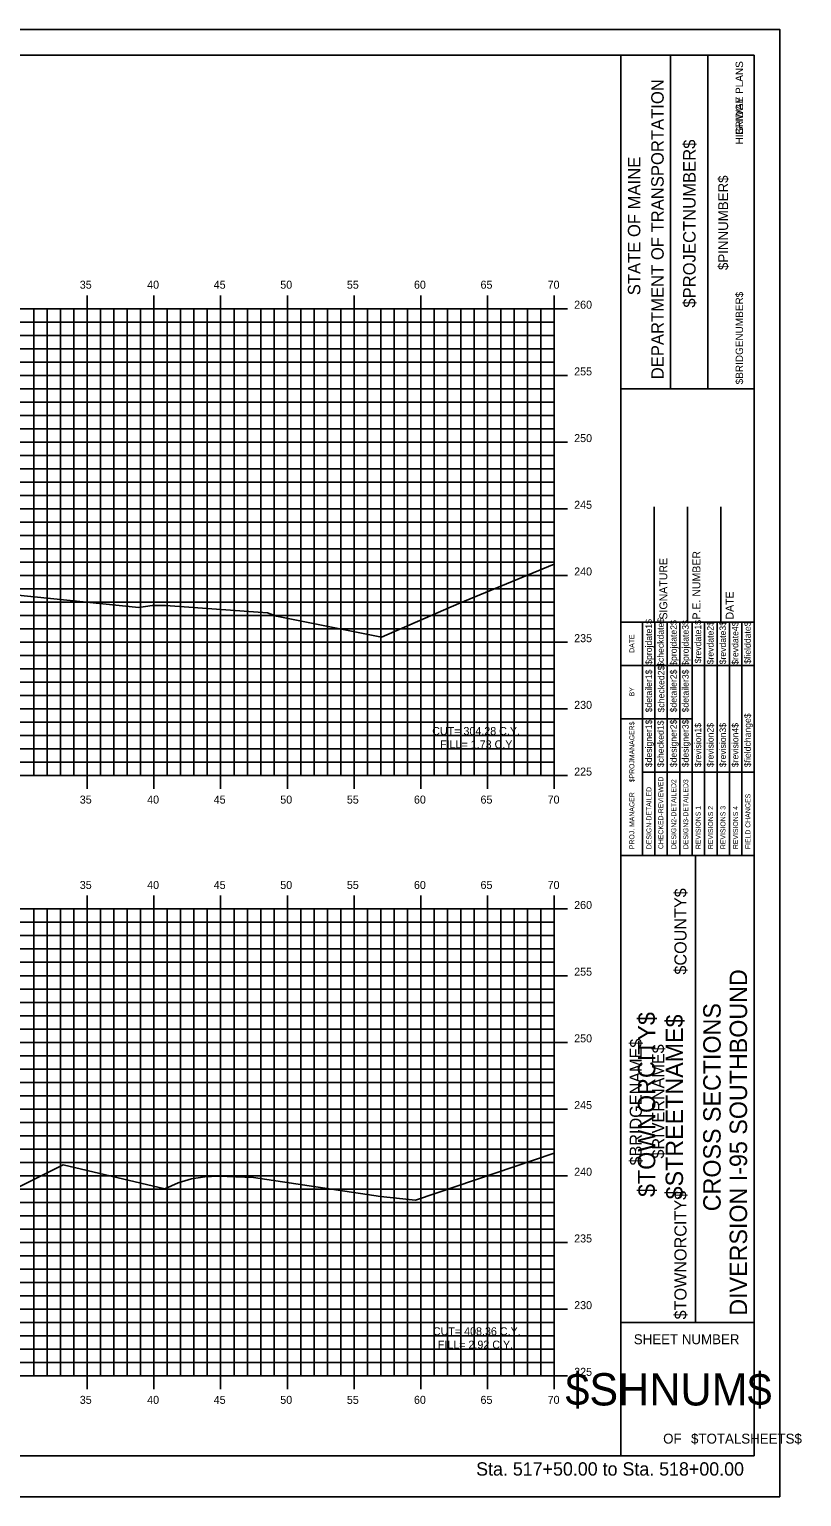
# Model space of a CAD drawing. Extents: x 1170543 to 1177585, y 609599 to 610623.
# Drawn here: x 1173835.4 to 1173893.3, y 609598.8 to 609708.8 of the extents above; entities that cross this region are included whole.
import ezdxf

# ---------------------------------------------------------------- set-up
doc = ezdxf.new("R2010")
doc.units = 0
for name, color, linetype in [('BORDER', 7, 'Continuous'), ('BRIDGE_TITLE', 7, 'Continuous'), ('D_Roadway_Centerline_Text', 7, 'Continuous'), ('H_V ANNOTATION', 7, 'Continuous'), ('HIGHWAY_TITLE', 7, 'Continuous'), ('MAJOR', 7, 'Continuous'), ('MINOR', 7, 'Continuous'), ('PLOT BOUNDARY', 7, 'Continuous'), ('S_Roadway_Centerline', 7, 'Continuous')]:
    doc.layers.add(name, color=color, linetype=linetype)

msp = doc.modelspace()

# ---------------------------------------------------------------- linework, layer by layer
at = {"layer": 'BORDER'}
for p, q in [((1173889.77, 609706.87), (1173729.77, 609706.87)), ((1173879.77, 609601.88), (1173879.77, 609706.88)), ((1173883.5, 609681.87), (1173883.5, 609706.87)), ((1173886.3, 609681.87), (1173886.3, 609706.87)), ((1173889.77, 609601.88), (1173889.77, 609706.88)), ((1173879.77, 609681.87), (1173889.77, 609681.87)), ((1173882.27, 609664.38), (1173882.27, 609673.02)), ((1173884.77, 609664.38), (1173884.77, 609673.02)), ((1173887.27, 609664.38), (1173887.27, 609673.02)), ((1173879.77, 609664.38), (1173889.77, 609664.38)), ((1173879.77, 609646.88), (1173889.77, 609646.88)), ((1173885.36, 609611.88), (1173885.36, 609646.88)), ((1173879.77, 609611.88), (1173889.77, 609611.88)), ((1173729.77, 609601.87), (1173889.77, 609601.87))]:
    msp.add_line(p, q, dxfattribs=at)
for points in [[(1173881.39, 609661.13), (1173881.39, 609664.38)], [(1173882.32, 609646.88), (1173882.32, 609664.38)], [(1173883.25, 609664.38), (1173883.25, 609646.88)], [(1173884.18, 609646.88), (1173884.18, 609664.38)], [(1173885.12, 609646.88), (1173885.12, 609664.38)], [(1173886.05, 609646.88), (1173886.05, 609664.38)], [(1173886.98, 609646.88), (1173886.98, 609664.38)], [(1173887.91, 609646.88), (1173887.91, 609664.38)], [(1173888.84, 609646.88), (1173888.84, 609664.38)], [(1173881.39, 609646.88), (1173881.39, 609663.67)], [(1173879.77, 609661.13), (1173889.77, 609661.13)], [(1173879.77, 609657.13), (1173881.39, 609657.13)], [(1173881.39, 609657.13), (1173885.12, 609657.13)], [(1173881.39, 609653.13), (1173889.77, 609653.13)]]:
    msp.add_lwpolyline(points, dxfattribs=at)
at = {"layer": 'MAJOR'}
for p, q in [((1173839.77, 609688.87), (1173839.77, 609687.87)), ((1173844.77, 609688.87), (1173844.77, 609687.87)), ((1173849.77, 609688.87), (1173849.77, 609687.87)), ((1173854.77, 609688.87), (1173854.77, 609687.87)), ((1173859.77, 609688.87), (1173859.77, 609687.87)), ((1173864.77, 609688.87), (1173864.77, 609687.87)), ((1173869.77, 609688.87), (1173869.77, 609687.87)), ((1173874.77, 609688.87), (1173874.77, 609687.87)), ((1173734.77, 609687.87), (1173874.77, 609687.87)), ((1173734.77, 609687.87), (1173874.77, 609687.87)), ((1173839.77, 609652.87), (1173839.77, 609687.87)), ((1173844.77, 609652.87), (1173844.77, 609687.87)), ((1173849.77, 609652.87), (1173849.77, 609687.87)), ((1173854.77, 609652.87), (1173854.77, 609687.87)), ((1173859.77, 609652.87), (1173859.77, 609687.87)), ((1173864.77, 609652.87), (1173864.77, 609687.87)), ((1173869.77, 609652.87), (1173869.77, 609687.87)), ((1173875.78, 609687.87), (1173873.77, 609687.87)), ((1173874.77, 609652.87), (1173874.77, 609687.87)), ((1173874.77, 609652.87), (1173874.77, 609687.87)), ((1173734.77, 609682.87), (1173874.77, 609682.87)), ((1173875.78, 609682.87), (1173873.77, 609682.87)), ((1173734.77, 609677.87), (1173874.77, 609677.87)), ((1173875.78, 609677.87), (1173873.77, 609677.87)), ((1173734.77, 609672.87), (1173874.77, 609672.87)), ((1173875.78, 609672.87), (1173873.77, 609672.87)), ((1173734.77, 609667.87), (1173874.77, 609667.87)), ((1173875.78, 609667.87), (1173873.77, 609667.87)), ((1173734.77, 609662.87), (1173874.77, 609662.87)), ((1173875.78, 609662.87), (1173873.77, 609662.87)), ((1173734.77, 609657.87), (1173874.77, 609657.87)), ((1173875.78, 609657.87), (1173873.77, 609657.87)), ((1173734.77, 609652.87), (1173874.77, 609652.87)), ((1173734.77, 609652.87), (1173874.77, 609652.87)), ((1173839.77, 609651.87), (1173839.77, 609652.87)), ((1173844.77, 609651.87), (1173844.77, 609652.87)), ((1173849.77, 609651.87), (1173849.77, 609652.87)), ((1173854.77, 609651.87), (1173854.77, 609652.87)), ((1173859.77, 609651.87), (1173859.77, 609652.87)), ((1173864.77, 609651.87), (1173864.77, 609652.87)), ((1173869.77, 609651.87), (1173869.77, 609652.87)), ((1173875.78, 609652.87), (1173873.77, 609652.87)), ((1173874.77, 609651.87), (1173874.77, 609652.87)), ((1173839.77, 609643.87), (1173839.77, 609642.87)), ((1173844.77, 609643.87), (1173844.77, 609642.87)), ((1173849.77, 609643.87), (1173849.77, 609642.87)), ((1173854.77, 609643.87), (1173854.77, 609642.87)), ((1173859.77, 609643.87), (1173859.77, 609642.87)), ((1173864.77, 609643.87), (1173864.77, 609642.87)), ((1173869.77, 609643.87), (1173869.77, 609642.87)), ((1173874.77, 609643.87), (1173874.77, 609642.87)), ((1173734.77, 609642.87), (1173874.77, 609642.87)), ((1173734.77, 609642.87), (1173874.77, 609642.87)), ((1173839.77, 609607.87), (1173839.77, 609642.87)), ((1173844.77, 609607.87), (1173844.77, 609642.87)), ((1173849.77, 609607.87), (1173849.77, 609642.87)), ((1173854.77, 609607.87), (1173854.77, 609642.87)), ((1173859.77, 609607.87), (1173859.77, 609642.87)), ((1173864.77, 609607.87), (1173864.77, 609642.87)), ((1173869.77, 609607.87), (1173869.77, 609642.87)), ((1173875.78, 609642.87), (1173873.77, 609642.87)), ((1173874.77, 609607.87), (1173874.77, 609642.87)), ((1173874.77, 609607.87), (1173874.77, 609642.87)), ((1173734.77, 609637.87), (1173874.77, 609637.87)), ((1173875.78, 609637.87), (1173873.77, 609637.87)), ((1173734.77, 609632.87), (1173874.77, 609632.87)), ((1173875.78, 609632.87), (1173873.77, 609632.87)), ((1173734.77, 609627.87), (1173874.77, 609627.87)), ((1173875.78, 609627.87), (1173873.77, 609627.87)), ((1173734.77, 609622.87), (1173874.77, 609622.87)), ((1173875.78, 609622.87), (1173873.77, 609622.87)), ((1173734.77, 609617.87), (1173874.77, 609617.87)), ((1173875.78, 609617.87), (1173873.77, 609617.87)), ((1173734.77, 609612.87), (1173874.77, 609612.87)), ((1173875.78, 609612.87), (1173873.77, 609612.87)), ((1173734.77, 609607.87), (1173874.77, 609607.87)), ((1173734.77, 609607.87), (1173874.77, 609607.87)), ((1173839.77, 609606.87), (1173839.77, 609607.87)), ((1173844.77, 609606.87), (1173844.77, 609607.87)), ((1173849.77, 609606.87), (1173849.77, 609607.87)), ((1173854.77, 609606.87), (1173854.77, 609607.87)), ((1173859.77, 609606.87), (1173859.77, 609607.87)), ((1173864.77, 609606.87), (1173864.77, 609607.87)), ((1173869.77, 609606.87), (1173869.77, 609607.87)), ((1173875.78, 609607.87), (1173873.77, 609607.87)), ((1173874.77, 609606.87), (1173874.77, 609607.87))]:
    msp.add_line(p, q, dxfattribs=at)
at = {"layer": 'MINOR'}
for p, q in [((1173835.77, 609652.87), (1173835.77, 609687.87)), ((1173836.77, 609652.87), (1173836.77, 609687.87)), ((1173837.77, 609652.87), (1173837.77, 609687.87)), ((1173838.77, 609652.87), (1173838.77, 609687.87)), ((1173840.77, 609652.87), (1173840.77, 609687.87)), ((1173841.77, 609652.87), (1173841.77, 609687.87)), ((1173842.77, 609652.87), (1173842.77, 609687.87)), ((1173843.77, 609652.87), (1173843.77, 609687.87)), ((1173845.77, 609652.87), (1173845.77, 609687.87)), ((1173846.77, 609652.87), (1173846.77, 609687.87)), ((1173847.77, 609652.87), (1173847.77, 609687.87)), ((1173848.77, 609652.87), (1173848.77, 609687.87)), ((1173850.77, 609652.87), (1173850.77, 609687.87)), ((1173851.77, 609652.87), (1173851.77, 609687.87)), ((1173852.77, 609652.87), (1173852.77, 609687.87)), ((1173853.77, 609652.87), (1173853.77, 609687.87)), ((1173855.77, 609652.87), (1173855.77, 609687.87)), ((1173856.77, 609652.87), (1173856.77, 609687.87)), ((1173857.77, 609652.87), (1173857.77, 609687.87)), ((1173858.77, 609652.87), (1173858.77, 609687.87)), ((1173860.77, 609652.87), (1173860.77, 609687.87)), ((1173861.77, 609652.87), (1173861.77, 609687.87)), ((1173862.77, 609652.87), (1173862.77, 609687.87)), ((1173863.77, 609652.87), (1173863.77, 609687.87)), ((1173865.77, 609652.87), (1173865.77, 609687.87)), ((1173866.77, 609652.87), (1173866.77, 609687.87)), ((1173867.77, 609652.87), (1173867.77, 609687.87)), ((1173868.77, 609652.87), (1173868.77, 609687.87)), ((1173870.77, 609652.87), (1173870.77, 609687.87)), ((1173871.77, 609652.87), (1173871.77, 609687.87)), ((1173872.77, 609652.87), (1173872.77, 609687.87)), ((1173873.77, 609652.87), (1173873.77, 609687.87)), ((1173734.77, 609686.87), (1173874.77, 609686.87)), ((1173874.77, 609686.87), (1173873.77, 609686.87)), ((1173734.77, 609685.87), (1173874.77, 609685.87)), ((1173874.77, 609685.87), (1173873.77, 609685.87)), ((1173734.77, 609684.87), (1173874.77, 609684.87)), ((1173734.77, 609683.87), (1173874.77, 609683.87)), ((1173874.77, 609684.87), (1173873.77, 609684.87)), ((1173874.77, 609683.87), (1173873.77, 609683.87)), ((1173734.77, 609681.87), (1173874.77, 609681.87)), ((1173874.77, 609681.87), (1173873.77, 609681.87)), ((1173734.77, 609680.87), (1173874.77, 609680.87)), ((1173874.77, 609680.87), (1173873.77, 609680.87)), ((1173734.77, 609679.87), (1173874.77, 609679.87)), ((1173874.77, 609679.87), (1173873.77, 609679.87)), ((1173734.77, 609678.87), (1173874.77, 609678.87)), ((1173874.77, 609678.87), (1173873.77, 609678.87)), ((1173734.77, 609676.87), (1173874.77, 609676.87)), ((1173874.77, 609676.87), (1173873.77, 609676.87)), ((1173734.77, 609675.87), (1173874.77, 609675.87)), ((1173874.77, 609675.87), (1173873.77, 609675.87)), ((1173734.77, 609674.87), (1173874.77, 609674.87)), ((1173874.77, 609674.87), (1173873.77, 609674.87)), ((1173734.77, 609673.87), (1173874.77, 609673.87)), ((1173874.77, 609673.87), (1173873.77, 609673.87)), ((1173734.77, 609671.87), (1173874.77, 609671.87)), ((1173874.77, 609671.87), (1173873.77, 609671.87)), ((1173734.77, 609670.87), (1173874.77, 609670.87)), ((1173874.77, 609670.87), (1173873.77, 609670.87)), ((1173734.77, 609669.87), (1173874.77, 609669.87)), ((1173874.77, 609669.87), (1173873.77, 609669.87)), ((1173734.77, 609668.87), (1173874.77, 609668.87)), ((1173874.77, 609668.87), (1173873.77, 609668.87)), ((1173734.77, 609666.87), (1173874.77, 609666.87)), ((1173874.77, 609666.87), (1173873.77, 609666.87)), ((1173734.77, 609665.87), (1173874.77, 609665.87)), ((1173874.77, 609665.87), (1173873.77, 609665.87)), ((1173734.77, 609664.87), (1173874.77, 609664.87)), ((1173874.77, 609664.87), (1173873.77, 609664.87)), ((1173734.77, 609663.87), (1173874.77, 609663.87)), ((1173874.77, 609663.87), (1173873.77, 609663.87)), ((1173734.77, 609661.87), (1173874.77, 609661.87)), ((1173874.77, 609661.87), (1173873.77, 609661.87)), ((1173734.77, 609660.87), (1173874.77, 609660.87)), ((1173874.77, 609660.87), (1173873.77, 609660.87)), ((1173734.77, 609659.87), (1173874.77, 609659.87)), ((1173874.77, 609659.87), (1173873.77, 609659.87)), ((1173734.77, 609658.87), (1173874.77, 609658.87)), ((1173874.77, 609658.87), (1173873.77, 609658.87)), ((1173734.77, 609656.87), (1173874.77, 609656.87)), ((1173874.77, 609656.87), (1173873.77, 609656.87)), ((1173734.77, 609655.87), (1173874.77, 609655.87)), ((1173874.77, 609655.87), (1173873.77, 609655.87)), ((1173734.77, 609654.87), (1173874.77, 609654.87)), ((1173874.77, 609654.87), (1173873.77, 609654.87)), ((1173734.77, 609653.87), (1173874.77, 609653.87)), ((1173874.77, 609653.87), (1173873.77, 609653.87)), ((1173835.77, 609607.87), (1173835.77, 609642.87)), ((1173836.77, 609607.87), (1173836.77, 609642.87)), ((1173837.77, 609607.87), (1173837.77, 609642.87)), ((1173838.77, 609607.87), (1173838.77, 609642.87)), ((1173840.77, 609607.87), (1173840.77, 609642.87)), ((1173841.77, 609607.87), (1173841.77, 609642.87)), ((1173842.77, 609607.87), (1173842.77, 609642.87)), ((1173843.77, 609607.87), (1173843.77, 609642.87)), ((1173845.77, 609607.87), (1173845.77, 609642.87)), ((1173846.77, 609607.87), (1173846.77, 609642.87)), ((1173847.77, 609607.87), (1173847.77, 609642.87)), ((1173848.77, 609607.87), (1173848.77, 609642.87)), ((1173850.77, 609607.87), (1173850.77, 609642.87)), ((1173851.77, 609607.87), (1173851.77, 609642.87)), ((1173852.77, 609607.87), (1173852.77, 609642.87)), ((1173853.77, 609607.87), (1173853.77, 609642.87)), ((1173855.77, 609607.87), (1173855.77, 609642.87)), ((1173856.77, 609607.87), (1173856.77, 609642.87)), ((1173857.77, 609607.87), (1173857.77, 609642.87)), ((1173858.77, 609607.87), (1173858.77, 609642.87)), ((1173860.77, 609607.87), (1173860.77, 609642.87)), ((1173861.77, 609607.87), (1173861.77, 609642.87)), ((1173862.77, 609607.87), (1173862.77, 609642.87)), ((1173863.77, 609607.87), (1173863.77, 609642.87)), ((1173865.77, 609607.87), (1173865.77, 609642.87)), ((1173866.77, 609607.87), (1173866.77, 609642.87)), ((1173867.77, 609607.87), (1173867.77, 609642.87)), ((1173868.77, 609607.87), (1173868.77, 609642.87)), ((1173870.77, 609607.87), (1173870.77, 609642.87)), ((1173871.77, 609607.87), (1173871.77, 609642.87)), ((1173872.77, 609607.87), (1173872.77, 609642.87)), ((1173873.77, 609607.87), (1173873.77, 609642.87)), ((1173734.77, 609641.87), (1173874.77, 609641.87)), ((1173874.77, 609641.87), (1173873.77, 609641.87)), ((1173734.77, 609640.87), (1173874.77, 609640.87)), ((1173734.77, 609639.87), (1173874.77, 609639.87)), ((1173874.77, 609640.87), (1173873.77, 609640.87)), ((1173874.77, 609639.87), (1173873.77, 609639.87)), ((1173734.77, 609638.87), (1173874.77, 609638.87)), ((1173874.77, 609638.87), (1173873.77, 609638.87)), ((1173734.77, 609636.87), (1173874.77, 609636.87)), ((1173874.77, 609636.87), (1173873.77, 609636.87)), ((1173734.77, 609635.87), (1173874.77, 609635.87)), ((1173874.77, 609635.87), (1173873.77, 609635.87)), ((1173734.77, 609634.87), (1173874.77, 609634.87)), ((1173874.77, 609634.87), (1173873.77, 609634.87)), ((1173734.77, 609633.87), (1173874.77, 609633.87)), ((1173874.77, 609633.87), (1173873.77, 609633.87)), ((1173734.77, 609631.87), (1173874.77, 609631.87)), ((1173874.77, 609631.87), (1173873.77, 609631.87)), ((1173734.77, 609630.87), (1173874.77, 609630.87)), ((1173874.77, 609630.87), (1173873.77, 609630.87)), ((1173734.77, 609629.87), (1173874.77, 609629.87)), ((1173734.77, 609628.87), (1173874.77, 609628.87)), ((1173874.77, 609629.87), (1173873.77, 609629.87)), ((1173874.77, 609628.87), (1173873.77, 609628.87)), ((1173734.77, 609626.87), (1173874.77, 609626.87)), ((1173874.77, 609626.87), (1173873.77, 609626.87)), ((1173734.77, 609625.87), (1173874.77, 609625.87)), ((1173874.77, 609625.87), (1173873.77, 609625.87)), ((1173734.77, 609624.87), (1173874.77, 609624.87)), ((1173874.77, 609624.87), (1173873.77, 609624.87)), ((1173734.77, 609623.87), (1173874.77, 609623.87)), ((1173874.77, 609623.87), (1173873.77, 609623.87)), ((1173734.77, 609621.87), (1173874.77, 609621.87)), ((1173874.77, 609621.87), (1173873.77, 609621.87)), ((1173734.77, 609620.87), (1173874.77, 609620.87)), ((1173874.77, 609620.87), (1173873.77, 609620.87)), ((1173734.77, 609619.87), (1173874.77, 609619.87)), ((1173874.77, 609619.87), (1173873.77, 609619.87)), ((1173734.77, 609618.87), (1173874.77, 609618.87)), ((1173874.77, 609618.87), (1173873.77, 609618.87)), ((1173734.77, 609616.87), (1173874.77, 609616.87)), ((1173874.77, 609616.87), (1173873.77, 609616.87)), ((1173734.77, 609615.87), (1173874.77, 609615.87)), ((1173874.77, 609615.87), (1173873.77, 609615.87)), ((1173734.77, 609614.87), (1173874.77, 609614.87)), ((1173874.77, 609614.87), (1173873.77, 609614.87)), ((1173734.77, 609613.87), (1173874.77, 609613.87)), ((1173874.77, 609613.87), (1173873.77, 609613.87)), ((1173734.77, 609611.87), (1173874.77, 609611.87)), ((1173874.77, 609611.87), (1173873.77, 609611.87)), ((1173734.77, 609610.87), (1173874.77, 609610.87)), ((1173874.77, 609610.87), (1173873.77, 609610.87)), ((1173734.77, 609609.87), (1173874.77, 609609.87)), ((1173874.77, 609609.87), (1173873.77, 609609.87)), ((1173734.77, 609608.87), (1173874.77, 609608.87)), ((1173874.77, 609608.87), (1173873.77, 609608.87))]:
    msp.add_line(p, q, dxfattribs=at)
at = {"layer": 'PLOT BOUNDARY'}
msp.add_lwpolyline([(1173721.68, 609598.81), (1173891.68, 609598.81), (1173891.68, 609708.81), (1173721.68, 609708.81)], close=True, dxfattribs=at)
at = {"layer": 'S_Roadway_Centerline'}
for points in [[(1173834.31, 609666.42), (1173843.63, 609665.47), (1173844.63, 609665.61), (1173844.64, 609665.61), (1173845.64, 609665.61), (1173853.28, 609665.08), (1173853.96, 609664.81), (1173861.82, 609663.25), (1173867.63, 609665.77), (1173874.77, 609668.73)], [(1173829.23, 609619.34), (1173837.96, 609623.7), (1173837.96, 609623.7), (1173837.96, 609623.7), (1173845.59, 609621.9), (1173846.59, 609622.33), (1173847.59, 609622.63), (1173848.59, 609622.79), (1173849.59, 609622.83), (1173849.59, 609622.83), (1173852.23, 609622.73), (1173861.76, 609621.32), (1173864.38, 609621.05), (1173874.77, 609624.56)]]:
    msp.add_lwpolyline(points, dxfattribs=at)

# ---------------------------------------------------------------- texts
at = {"layer": 'BORDER'}
for s, height, rotation, p in [('DEPARTMENT OF TRANSPORTATION', 0.9318, 90, (1173882.98, 609682.58)), ('$PROJECTNUMBER$', 0.9318, 90, (1173885.37, 609687.95)), ('STATE OF MAINE', 0.9318, 90, (1173881.23, 609688.88)), ('$PINNUMBER$', 0.7453, 90, (1173887.81, 609690.77)), ('P.E. NUMBER', 0.5906, 90, (1173885.73, 609664.57)), ('SIGNATURE', 0.591, 90, (1173883.25, 609664.57)), ('DATE', 0.591, 90, (1173888.22, 609664.57)), ('$projdate1$', 0.4845, 90, (1173882.1, 609661.18)), ('$checkdate$', 0.4845, 90, (1173882.99, 609661.02)), ('$projdate2$', 0.4845, 90, (1173883.96, 609661.1)), ('$projdate3$', 0.4845, 90, (1173884.85, 609661.1)), ('$revdate1$', 0.485, 90, (1173885.79, 609661.29)), ('$revdate2$', 0.485, 90, (1173886.72, 609661.21)), ('$revdate3$', 0.485, 90, (1173887.65, 609661.21)), ('$revdate4$', 0.485, 90, (1173888.58, 609661.18)), ('$fielddate$', 0.4845, 90, (1173889.51, 609661.25)), ('DATE', 0.371, 90, (1173880.78, 609662.08)), ('$detailer1$', 0.4845, 90, (1173882.1, 609657.61)), ('$checked2$', 0.485, 90, (1173883.03, 609657.61)), ('$detailer2$', 0.4845, 90, (1173883.96, 609657.61)), ('$detailer3$', 0.4845, 90, (1173884.85, 609657.61)), ('BY', 0.371, 90, (1173880.78, 609658.81)), ('$fieldchange$', 0.4845, 90, (1173889.51, 609653.5)), ('$PROJMANAGER$', 0.3727, 90, (1173880.78, 609652.37)), ('$designer1$', 0.4845, 90, (1173882.1, 609653.5)), ('$checked1$', 0.485, 90, (1173882.99, 609653.5)), ('$designer2$', 0.4845, 90, (1173883.96, 609653.5)), ('$designer3$', 0.4845, 90, (1173884.85, 609653.5)), ('$revision1$', 0.4845, 90, (1173885.79, 609653.5)), ('$revision2$', 0.4845, 90, (1173886.72, 609653.5)), ('$revision3$', 0.4845, 90, (1173887.65, 609653.5)), ('$revision4$', 0.4845, 90, (1173888.58, 609653.5)), ('CHECKED-REVIEWED', 0.3727, 90, (1173882.95, 609647.36)), ('DESIGN2-DETAILED2', 0.3727, 90, (1173883.92, 609647.36)), ('DESIGN3-DETAILED3', 0.3727, 90, (1173884.82, 609647.36)), ('PROJ. MANAGER', 0.3727, 90, (1173880.78, 609647.36)), ('DESIGN-DETAILED', 0.3727, 90, (1173882.06, 609647.36)), ('FIELD CHANGES', 0.3727, 90, (1173889.48, 609647.36)), ('REVISIONS 1', 0.3727, 90, (1173885.75, 609647.36)), ('REVISIONS 2', 0.3727, 90, (1173886.68, 609647.36)), ('REVISIONS 3', 0.3727, 90, (1173887.61, 609647.36)), ('REVISIONS 4', 0.3727, 90, (1173888.55, 609647.36)), ('DIVERSION I-95 SOUTHBOUND', 1.3043, 90, (1173889.23, 609612.38)), ('CROSS SECTIONS', 1.3043, 90, (1173887.25, 609620.21)), ('SHEET NUMBER', 0.7453, 360, (1173880.74, 609610.24)), ('$SHNUM$', 2.419, 360, (1173875.61, 609605.65)), ('OF', 0.745, 360, (1173882.94, 609602.79)), ('$TOTALSHEETS$', 0.7453, 360, (1173885.03, 609602.79))]:
    msp.add_text(s, height=height, rotation=rotation, dxfattribs=at).set_placement(p)
at = {"layer": 'BRIDGE_TITLE'}
for s, height, p in [('BRIDGE PLANS', 0.559, (1173888.93, 609700.9)), ('$BRIDGENUMBER$', 0.559, (1173888.93, 609682.2)), ('$COUNTY$', 0.907, (1173884.69, 609637.95)), ('$BRIDGENAME$', 0.9072, (1173881.34, 609623.64)), ('$RIVERNAME$', 0.9072, (1173883.02, 609624.16)), ('$TOWNORCITY$', 0.9072, (1173884.69, 609612.1))]:
    msp.add_text(s, height=height, rotation=90, dxfattribs=at).set_placement(p)
at = {"layer": 'D_Roadway_Centerline_Text'}
for s, p in [('CUT= 304.28 C.Y.', (1173865.63, 609655.91)), ('FILL= 1.73 C.Y.', (1173866.22, 609654.91)), ('CUT= 408.36 C.Y.', (1173865.68, 609610.91)), ('FILL= 2.92 C.Y.', (1173866.05, 609609.91))]:
    msp.add_text(s, height=0.6, dxfattribs=at).set_placement(p)
at = {"layer": 'H_V ANNOTATION'}
for s, height, p in [('35', 0.6, (1173839.21, 609689.37)), ('40', 0.6, (1173844.26, 609689.37)), ('45', 0.6, (1173849.25, 609689.37)), ('50', 0.6, (1173854.24, 609689.37)), ('55', 0.6, (1173859.23, 609689.37)), ('60', 0.6, (1173864.26, 609689.37)), ('65', 0.6, (1173869.25, 609689.37)), ('70', 0.6, (1173874.28, 609689.37)), ('260', 0.6, (1173876.27, 609687.87)), ('255', 0.6, (1173876.27, 609682.87)), ('250', 0.6, (1173876.27, 609677.87)), ('245', 0.6, (1173876.27, 609672.87)), ('240', 0.6, (1173876.27, 609667.87)), ('235', 0.6, (1173876.27, 609662.87)), ('230', 0.6, (1173876.27, 609657.87)), ('225', 0.6, (1173876.27, 609652.87)), ('35', 0.6, (1173839.21, 609650.77)), ('40', 0.6, (1173844.26, 609650.77)), ('45', 0.6, (1173849.25, 609650.77)), ('50', 0.6, (1173854.24, 609650.77)), ('55', 0.6, (1173859.23, 609650.77)), ('60', 0.6, (1173864.26, 609650.77)), ('65', 0.6, (1173869.25, 609650.77)), ('70', 0.6, (1173874.28, 609650.77)), ('35', 0.6, (1173839.21, 609644.37)), ('40', 0.6, (1173844.26, 609644.37)), ('45', 0.6, (1173849.25, 609644.37)), ('50', 0.6, (1173854.24, 609644.37)), ('55', 0.6, (1173859.23, 609644.37)), ('60', 0.6, (1173864.26, 609644.37)), ('65', 0.6, (1173869.25, 609644.37)), ('70', 0.6, (1173874.28, 609644.37)), ('260', 0.6, (1173876.27, 609642.87)), ('255', 0.6, (1173876.27, 609637.87)), ('250', 0.6, (1173876.27, 609632.87)), ('245', 0.6, (1173876.27, 609627.87)), ('240', 0.6, (1173876.27, 609622.87)), ('235', 0.6, (1173876.27, 609617.87)), ('230', 0.6, (1173876.27, 609612.87)), ('225', 0.6, (1173876.27, 609607.87)), ('35', 0.6, (1173839.21, 609605.77)), ('40', 0.6, (1173844.26, 609605.77)), ('45', 0.6, (1173849.25, 609605.77)), ('50', 0.6, (1173854.24, 609605.77)), ('55', 0.6, (1173859.23, 609605.77)), ('60', 0.6, (1173864.26, 609605.77)), ('65', 0.6, (1173869.25, 609605.77)), ('70', 0.6, (1173874.28, 609605.77)), ('Sta. 517+50.00 to Sta. 518+00.00', 1.0002, (1173868.92, 609600.39))]:
    msp.add_text(s, height=height, dxfattribs=at).set_placement(p)
at = {"layer": 'HIGHWAY_TITLE'}
for s, height, p in [('HIGHWAY PLANS', 0.559, (1173888.93, 609700.19)), ('$TOWNORCITY$', 1.3043, (1173882.35, 609621.28)), ('$STREETNAME$', 1.3043, (1173884.43, 609621.1))]:
    msp.add_text(s, height=height, rotation=90, dxfattribs=at).set_placement(p)

doc.saveas('drawing.dxf')
